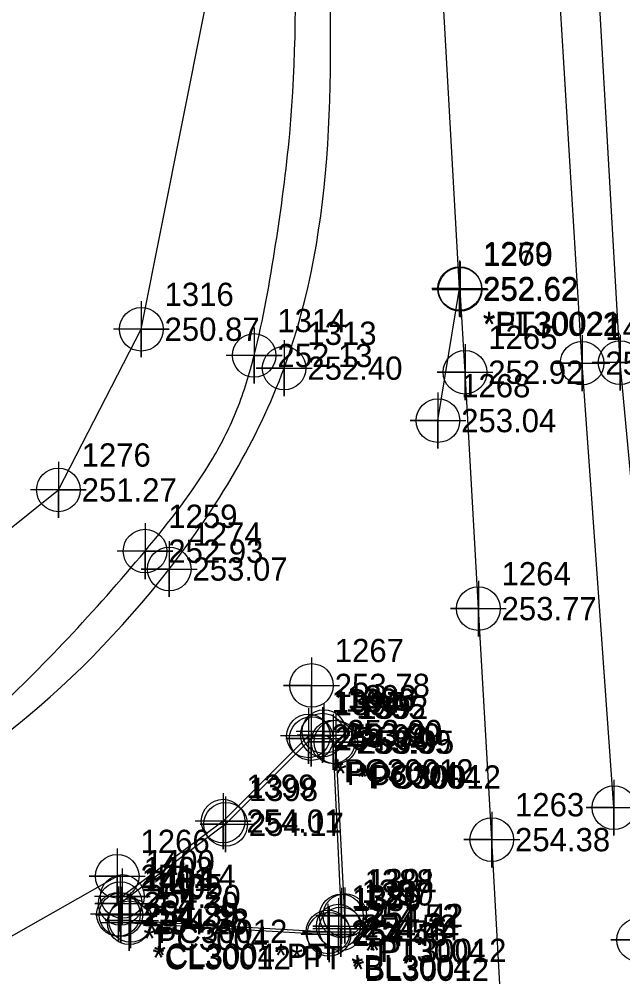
# Model space of a CAD drawing. Extents: x 2130962 to 2131465, y 643052 to 644206.
# Drawn here: x 2131195.3 to 2131260.2, y 643203.3 to 643306.2 of the extents above; entities that cross this region are included whole.
import ezdxf

# ---------------------------------------------------------------- set-up
doc = ezdxf.new("R2010")
doc.units = 0
for name, color, linetype in [('Exist DTM Breakline', 7, 'Continuous'), ('Exist DTM Breakline Cogo Elevation', 7, 'Continuous'), ('Exist DTM Breakline Cogo Number', 7, 'Continuous'), ('Exist DTM Breakline Cogo Point CELL', 7, 'Continuous'), ('Exist Roads Curbs', 7, 'Continuous'), ('Exist Roads Curbs Cogo Comment', 7, 'Continuous'), ('Exist Roads Curbs Cogo Elevation', 7, 'Continuous'), ('Exist Roads Curbs Cogo Number', 7, 'Continuous'), ('Exist Roads Curbs Cogo Point CELL', 7, 'Continuous'), ('Exist Roads EOP', 7, 'Continuous'), ('Exist Roads EOP Cogo Comment', 7, 'Continuous'), ('Exist Roads EOP Cogo Elevation', 7, 'Continuous'), ('Exist Roads EOP Cogo Number', 7, 'Continuous'), ('Exist Roads EOP Cogo Point CELL', 7, 'Continuous'), ('Exist Roads EOT', 7, 'Continuous'), ('Exist Roads EOT Cogo Comment', 7, 'Continuous'), ('Exist Roads EOT Cogo Elevation', 7, 'Continuous'), ('Exist Roads EOT Cogo Number', 7, 'Continuous'), ('Exist Roads EOT Cogo Point CELL', 7, 'Continuous')]:
    doc.layers.add(name, color=color, linetype=linetype)

msp = doc.modelspace()

# ---------------------------------------------------------------- linework, layer by layer
at = {"layer": 'Exist DTM Breakline'}
msp.add_lwpolyline([(2131000.2707, 643222.2884), (2131049.3172, 643219.2511), (2131099.5024, 643216.1866), (2131123.0232, 643217.8518), (2131146.7721, 643223.5416), (2131166.8509, 643229.4959), (2131199.4918, 643255.6512), (2131208.4065, 643272.9132), (2131217.3052, 643317.6851), (2131214.0619, 643367.4973), (2131211.0353, 643416.1836)], dxfattribs=at)
at = {"layer": 'Exist DTM Breakline Cogo Point CELL'}
for points in [[(2131208.4065, 643275.9132), (2131208.4065, 643269.9132), (2131208.4065, 643272.9132), (2131211.4065, 643272.9132), (2131205.4065, 643272.9132)], [(2131199.4918, 643258.6512), (2131199.4918, 643252.6512), (2131199.4918, 643255.6512), (2131202.4918, 643255.6512), (2131196.4918, 643255.6512)]]:
    msp.add_lwpolyline(points, dxfattribs=at)
for centre in [(2131208.4065, 643272.9132), (2131199.4918, 643255.6512)]:
    msp.add_circle(centre, 2.344, dxfattribs=at)
at = {"layer": 'Exist Roads Curbs'}
for points in [[(2131226.6806, 643228.9253), (2131217.4669, 643219.7163), (2131206.1479, 643211.206)], [(2131226.6806, 643228.9253), (2131226.6806, 643228.9253)], [(2131229.9116, 643209.8755), (2131229.0208, 643228.5735)], [(2131207.2468, 643209.3929), (2131228.4737, 643208.158)]]:
    msp.add_lwpolyline(points, dxfattribs=at)
msp.add_arc((2131227.7053, 643227.7822), 1.5352, 31.031398, 131.874567, dxfattribs=at)
at = {"layer": 'Exist Roads Curbs Cogo Point CELL'}
for points in [[(2131227.8758, 643232.3078), (2131227.8758, 643226.3078), (2131227.8758, 643229.3078), (2131225.1458, 643229.3078), (2131230.8758, 643229.3078)], [(2131226.6806, 643231.9253), (2131226.6806, 643225.9253), (2131226.6806, 643228.9253), (2131223.9506, 643228.9253), (2131229.6806, 643228.9253)], [(2131229.0208, 643231.5735), (2131229.0208, 643225.5735), (2131229.0208, 643228.5735), (2131226.2908, 643228.5735), (2131232.0208, 643228.5735)], [(2131217.4669, 643222.7163), (2131217.4669, 643216.7163), (2131217.4669, 643219.7163), (2131214.7369, 643219.7163), (2131220.4669, 643219.7163)], [(2131206.1479, 643214.206), (2131206.1479, 643208.206), (2131206.1479, 643211.206), (2131203.4179, 643211.206), (2131209.1479, 643211.206)], [(2131206.2138, 643213.0076), (2131206.2138, 643207.0076), (2131206.2138, 643210.0076), (2131203.4838, 643210.0076), (2131209.2138, 643210.0076)], [(2131229.9116, 643212.8755), (2131229.9116, 643206.8755), (2131229.9116, 643209.8755), (2131227.1816, 643209.8755), (2131232.9116, 643209.8755)], [(2131207.2468, 643212.3929), (2131207.2468, 643206.3929), (2131207.2468, 643209.3929), (2131204.5168, 643209.3929), (2131210.2468, 643209.3929)], [(2131229.5866, 643211.7744), (2131229.5866, 643205.7744), (2131229.5866, 643208.7744), (2131226.8566, 643208.7744), (2131232.5866, 643208.7744)], [(2131228.4737, 643211.158), (2131228.4737, 643205.158), (2131228.4737, 643208.158), (2131225.7437, 643208.158), (2131231.4737, 643208.158)]]:
    msp.add_lwpolyline(points, dxfattribs=at)
for centre in [(2131226.6806, 643228.9253), (2131227.8758, 643229.3078), (2131229.0208, 643228.5735), (2131217.4669, 643219.7163), (2131206.1479, 643211.206), (2131206.2138, 643210.0076), (2131207.2468, 643209.3929), (2131229.9116, 643209.8755), (2131229.5866, 643208.7744), (2131228.4737, 643208.158)]:
    msp.add_circle(centre, 2.344, dxfattribs=at)
at = {"layer": 'Exist Roads EOP'}
for points in [[(2131264.2715, 643222.5647), (2131259.8757, 643269.3254), (2131257.0196, 643319.4043), (2131254.2561, 643369.6499), (2131250.0777, 643419.4187), (2131246.1511, 643469.0294), (2131240.8382, 643519.1271), (2131234.3674, 643568.5584), (2131226.3321, 643620.1808), (2131217.0271, 643668.7116), (2131205.6213, 643717.607), (2131192.0578, 643767.2595), (2131177.9714, 643815.0911), (2131162.2913, 643862.9344), (2131145.3604, 643910.8486), (2131126.9113, 643957.2915), (2131112.3691, 643996.1228)], [(2131226.3753, 643229.2119), (2131217.1988, 643220.0584), (2131206.3645, 643211.9638)], [(2131226.3753, 643229.2119), (2131226.3753, 643229.2119)], [(2131230.2874, 643209.9228), (2131229.3155, 643228.5471)], [(2131207.1087, 643209.1386), (2131228.5924, 643207.8908)]]:
    msp.add_lwpolyline(points, dxfattribs=at)
msp.add_spline([(2131166.2495, 643216.6951), (2131171.8131, 643218.7244), (2131182.3713, 643223.9726), (2131191.8117, 643231.1489), (2131200.5013, 643239.6993), (2131208.8071, 643249.0697), (2131216.0672, 643259.0032), (2131218.7188, 643264.347), (2131220.5363, 643270.0958), (2131222.8445, 643282.0077), (2131224.3583, 643293.9245), (2131224.8763, 643317.7904), (2131222.0632, 643367.6716), (2131218.5448, 643416.8114), (2131214.3187, 643466.3462), (2131209.1735, 643515.6666), (2131202.7939, 643565.1545), (2131195.0475, 643613.9937), (2131186.4014, 643662.4763), (2131176.0113, 643711.405), (2131164.6154, 643759.8896), (2131151.874, 643807.8526), (2131137.8554, 643855.4065), (2131122.5733, 643902.8574), (2131105.9622, 643949.4862), (2131091.5349, 643988.0437)], degree=3, dxfattribs=at)
at = {"layer": 'Exist Roads EOP Cogo Point CELL'}
for points in [[(2131220.5363, 643273.0958), (2131220.5363, 643267.0958), (2131220.5363, 643270.0958), (2131223.5363, 643270.0958), (2131217.5363, 643270.0958)], [(2131259.8757, 643272.3254), (2131259.8757, 643266.3254), (2131259.8757, 643269.3254), (2131262.8757, 643269.3254), (2131256.8757, 643269.3254)], [(2131208.8071, 643252.0697), (2131208.8071, 643246.0697), (2131208.8071, 643249.0697), (2131211.8071, 643249.0697), (2131205.8071, 643249.0697)], [(2131228.0358, 643232.6796), (2131228.0358, 643226.6796), (2131228.0358, 643229.6796), (2131231.0358, 643229.6796), (2131225.0358, 643229.6796)], [(2131226.3753, 643232.2119), (2131226.3753, 643226.2119), (2131226.3753, 643229.2119), (2131229.3753, 643229.2119), (2131223.3753, 643229.2119)], [(2131229.3155, 643231.5471), (2131229.3155, 643225.5471), (2131229.3155, 643228.5471), (2131232.3155, 643228.5471), (2131226.3155, 643228.5471)], [(2131217.1988, 643223.0584), (2131217.1988, 643217.0584), (2131217.1988, 643220.0584), (2131220.1988, 643220.0584), (2131214.1988, 643220.0584)], [(2131206.3645, 643214.9638), (2131206.3645, 643208.9638), (2131206.3645, 643211.9638), (2131209.3645, 643211.9638), (2131203.3645, 643211.9638)], [(2131205.9466, 643213.0439), (2131205.9466, 643207.0439), (2131205.9466, 643210.0439), (2131208.9466, 643210.0439), (2131202.9466, 643210.0439)], [(2131230.2874, 643212.9228), (2131230.2874, 643206.9228), (2131230.2874, 643209.9228), (2131233.2874, 643209.9228), (2131227.2874, 643209.9228)], [(2131207.1087, 643212.1386), (2131207.1087, 643206.1386), (2131207.1087, 643209.1386), (2131210.1087, 643209.1386), (2131204.1087, 643209.1386)], [(2131228.5924, 643210.8908), (2131228.5924, 643204.8908), (2131228.5924, 643207.8908), (2131231.5924, 643207.8908), (2131225.5924, 643207.8908)], [(2131229.857, 643211.4836), (2131229.857, 643205.4836), (2131229.857, 643208.4836), (2131232.857, 643208.4836), (2131226.857, 643208.4836)]]:
    msp.add_lwpolyline(points, dxfattribs=at)
for centre in [(2131220.5363, 643270.0958), (2131259.8757, 643269.3254), (2131208.8071, 643249.0697), (2131226.3753, 643229.2119), (2131228.0358, 643229.6796), (2131229.3155, 643228.5471), (2131217.1988, 643220.0584), (2131206.3645, 643211.9638), (2131205.9466, 643210.0439), (2131230.2874, 643209.9228), (2131207.1087, 643209.1386), (2131229.857, 643208.4836), (2131228.5924, 643207.8908)]:
    msp.add_circle(centre, 2.344, dxfattribs=at)
at = {"layer": 'Exist Roads EOT'}
msp.add_line((2131259.2129, 643221.5063), (2131255.7894, 643269.2666), dxfattribs=at)
for points in [[(2131255.7894, 643269.2666), (2131252.7511, 643319.2443), (2131249.9083, 643369.5477), (2131246.3502, 643419.1778), (2131242.1933, 643468.6938), (2131237.0867, 643518.9193), (2131230.8671, 643568.2588), (2131222.7066, 643619.1047), (2131213.6442, 643668.3078), (2131202.755, 643717.0933), (2131189.234, 643766.4577), (2131174.9499, 643814.1787), (2131159.2111, 643861.933), (2131141.9103, 643909.6722), (2131123.7008, 643956.0828), (2131104.9436, 644003.1503), (2131086.2706, 644048.8072), (2131065.6997, 644094.9191), (2131044.3618, 644140.0645), (2131021.6804, 644185.4526)], [(2131240.2947, 643263.0991), (2131242.6265, 643277.2895), (2131240.2984, 643318.6562), (2131237.6994, 643363.706)], [(2131179.5807, 643199.2911), (2131198.9377, 643198.0762), (2131247.357, 643195.3668), (2131246.0808, 643218.0694), (2131244.6364, 643242.8933), (2131243.2031, 643268.2965), (2131242.6761, 643277.201)], [(2131179.5807, 643199.2911), (2131205.8187, 643214.1331)]]:
    msp.add_lwpolyline(points, dxfattribs=at)
msp.add_spline([(2131166.718, 643215.2083), (2131172.3866, 643217.1804), (2131211.4056, 643247.1499), (2131223.758, 643268.7314), (2131228.3848, 643317.935), (2131225.533, 643367.8628), (2131222.2486, 643417.1873), (2131217.9619, 643466.6275), (2131212.8794, 643516.2377), (2131206.5633, 643565.5764), (2131198.9021, 643614.6757), (2131189.6851, 643663.4055), (2131179.3985, 643712.1311), (2131168.3085, 643760.7185), (2131155.755, 643808.9129), (2131141.6748, 643856.5528), (2131126.5354, 643904.2758), (2131110.3559, 643951.0191), (2131092.4533, 643998.1348), (2131073.722, 644043.631), (2131053.1654, 644089.359), (2131032.0052, 644134.0908), (2131009.0644, 644179.3802)], degree=3, dxfattribs=at)
at = {"layer": 'Exist Roads EOT Cogo Point CELL'}
for points in [[(2131242.6265, 643280.2895), (2131242.6265, 643274.2895), (2131242.6265, 643277.2895), (2131239.6265, 643277.2895), (2131245.6265, 643277.2895)], [(2131242.6761, 643280.201), (2131242.6761, 643274.201), (2131242.6761, 643277.201), (2131239.6761, 643277.201), (2131245.6761, 643277.201)], [(2131223.758, 643271.7314), (2131223.758, 643265.7314), (2131223.758, 643268.7314), (2131220.758, 643268.7314), (2131226.758, 643268.7314)], [(2131255.7894, 643272.2666), (2131255.7894, 643266.2666), (2131255.7894, 643269.2666), (2131252.7894, 643269.2666), (2131258.7894, 643269.2666)], [(2131243.2031, 643271.2965), (2131243.2031, 643265.2965), (2131243.2031, 643268.2965), (2131240.2031, 643268.2965), (2131246.2031, 643268.2965)], [(2131240.2947, 643266.0991), (2131240.2947, 643260.0991), (2131240.2947, 643263.0991), (2131237.2947, 643263.0991), (2131243.2947, 643263.0991)], [(2131211.4056, 643250.1499), (2131211.4056, 643244.1499), (2131211.4056, 643247.1499), (2131208.4056, 643247.1499), (2131214.4056, 643247.1499)], [(2131244.6364, 643245.8933), (2131244.6364, 643239.8933), (2131244.6364, 643242.8933), (2131241.6364, 643242.8933), (2131247.6364, 643242.8933)], [(2131226.7022, 643237.6427), (2131226.7022, 643231.6427), (2131226.7022, 643234.6427), (2131223.7022, 643234.6427), (2131229.7022, 643234.6427)], [(2131259.2129, 643224.5063), (2131259.2129, 643218.5063), (2131259.2129, 643221.5063), (2131256.2129, 643221.5063), (2131262.2129, 643221.5063)], [(2131246.0808, 643221.0694), (2131246.0808, 643215.0694), (2131246.0808, 643218.0694), (2131243.0808, 643218.0694), (2131249.0808, 643218.0694)], [(2131205.8187, 643217.1331), (2131205.8187, 643211.1331), (2131205.8187, 643214.1331), (2131202.8187, 643214.1331), (2131208.8187, 643214.1331)], [(2131261.865, 643210.302), (2131261.865, 643204.302), (2131261.865, 643207.302), (2131258.865, 643207.302), (2131264.865, 643207.302)]]:
    msp.add_lwpolyline(points, dxfattribs=at)
for centre in [(2131242.6265, 643277.2895), (2131242.6761, 643277.201), (2131255.7894, 643269.2666), (2131223.758, 643268.7314), (2131243.2031, 643268.2965), (2131240.2947, 643263.0991), (2131211.4056, 643247.1499), (2131244.6364, 643242.8933), (2131226.7022, 643234.6427), (2131259.2129, 643221.5063), (2131246.0808, 643218.0694), (2131205.8187, 643214.1331), (2131261.865, 643207.302)]:
    msp.add_circle(centre, 2.344, dxfattribs=at)

# ---------------------------------------------------------------- texts
at = {"layer": 'Exist DTM Breakline Cogo Elevation'}
for s, p in [('250.87', (2131210.9065, 643271.6632)), ('251.27', (2131201.9918, 643254.4012))]:
    msp.add_text(s, height=2.5, dxfattribs=at).set_placement(p)
at = {"layer": 'Exist DTM Breakline Cogo Number'}
for s, p in [('1316', (2131210.9065, 643275.4132)), ('1276', (2131201.9918, 643258.1512))]:
    msp.add_text(s, height=2.5, dxfattribs=at).set_placement(p)
at = {"layer": 'Exist Roads Curbs Cogo Comment'}
for s, p in [('*PC3004', (2131229.1806, 643223.9253)), ('*PC3004', (2131231.5208, 643223.5735)), ('*PC3004', (2131208.6479, 643206.206)), ('*CL3004*PT', (2131209.7468, 643204.3929)), ('*PT3004', (2131232.4116, 643204.8755)), ('*BL3004', (2131230.9737, 643203.158))]:
    msp.add_text(s, height=2.5, dxfattribs=at).set_placement(p)
at = {"layer": 'Exist Roads Curbs Cogo Elevation'}
for s, p in [('254.00', (2131229.1806, 643227.6753)), ('253.99', (2131230.3758, 643228.0578)), ('253.99', (2131231.5208, 643227.3235)), ('254.17', (2131219.9669, 643218.4663)), ('254.30', (2131208.6479, 643209.956)), ('254.35', (2131208.7138, 643208.7576)), ('254.38', (2131209.7468, 643208.1429)), ('254.52', (2131232.4116, 643208.6255)), ('254.53', (2131232.0866, 643207.5244)), ('254.56', (2131230.9737, 643206.908))]:
    msp.add_text(s, height=2.5, dxfattribs=at).set_placement(p)
at = {"layer": 'Exist Roads Curbs Cogo Number'}
for s, p in [('1396', (2131230.3758, 643231.8078)), ('1397', (2131229.1806, 643231.4253)), ('1395', (2131231.5208, 643231.0735)), ('1398', (2131219.9669, 643222.2163)), ('1403', (2131208.6479, 643213.706)), ('1404', (2131208.7138, 643212.5076)), ('1388', (2131232.4116, 643212.3755)), ('1405', (2131209.7468, 643211.8929)), ('1387', (2131232.0866, 643211.2744)), ('1386', (2131230.9737, 643210.658))]:
    msp.add_text(s, height=2.5, dxfattribs=at).set_placement(p)
at = {"layer": 'Exist Roads EOP Cogo Comment'}
for s, p in [('*PC30012', (2131228.8753, 643224.2119)), ('*PC30012', (2131231.8155, 643223.5471)), ('*PC30012', (2131208.8645, 643206.9638)), ('*CL30012*PT', (2131209.6087, 643204.1386)), ('*PT30012', (2131232.7874, 643204.9228)), ('*BL30012', (2131231.0924, 643202.8908))]:
    msp.add_text(s, height=2.5, dxfattribs=at).set_placement(p)
at = {"layer": 'Exist Roads EOP Cogo Elevation'}
for s, p in [('252.13', (2131223.0363, 643268.8458)), ('252.93', (2131211.3071, 643247.8197)), ('253.92', (2131228.8753, 643227.9619)), ('253.90', (2131230.5358, 643228.4296)), ('253.95', (2131231.8155, 643227.2971)), ('254.01', (2131219.6988, 643218.8084)), ('254.20', (2131208.8645, 643210.7138)), ('254.29', (2131208.4466, 643208.7939)), ('254.42', (2131232.7874, 643208.6728)), ('254.26', (2131209.6087, 643207.8886)), ('254.44', (2131232.357, 643207.2336)), ('254.43', (2131231.0924, 643206.6408))]:
    msp.add_text(s, height=2.5, dxfattribs=at).set_placement(p)
at = {"layer": 'Exist Roads EOP Cogo Number'}
for s, p in [('1314', (2131223.0363, 643272.5958)), ('1259', (2131211.3071, 643251.5697)), ('1393', (2131230.5358, 643232.1796)), ('1394', (2131228.8753, 643231.7119)), ('1392', (2131231.8155, 643231.0471)), ('1399', (2131219.6988, 643222.5584)), ('1400', (2131208.8645, 643214.4638)), ('1401', (2131208.4466, 643212.5439)), ('1391', (2131232.7874, 643212.4228)), ('1402', (2131209.6087, 643211.6386)), ('1389', (2131231.0924, 643210.3908)), ('1390', (2131232.357, 643210.9836))]:
    msp.add_text(s, height=2.5, dxfattribs=at).set_placement(p)
at = {"layer": 'Exist Roads EOT Cogo Comment'}
for s, p in [('*PT30021', (2131245.1265, 643272.2895)), ('*EL30022', (2131245.1761, 643272.201))]:
    msp.add_text(s, height=2.5, dxfattribs=at).set_placement(p)
at = {"layer": 'Exist Roads EOT Cogo Elevation'}
for s, p in [('252.62', (2131245.1265, 643276.0395)), ('252.62', (2131245.1761, 643275.951)), ('252.83', (2131258.2894, 643268.0166)), ('252.40', (2131226.258, 643267.4814)), ('252.92', (2131245.7031, 643267.0465)), ('253.04', (2131242.7947, 643261.8491)), ('253.07', (2131213.9056, 643245.8999)), ('253.77', (2131247.1364, 643241.6433)), ('253.78', (2131229.2022, 643233.3927)), ('254.38', (2131248.5808, 643216.8194)), ('254.14', (2131208.3187, 643212.8831))]:
    msp.add_text(s, height=2.5, dxfattribs=at).set_placement(p)
at = {"layer": 'Exist Roads EOT Cogo Number'}
for s, p in [('1269', (2131245.1265, 643279.7895)), ('1270', (2131245.1761, 643279.701)), ('1313', (2131226.258, 643271.2314)), ('1406', (2131258.2894, 643271.7666)), ('1265', (2131245.7031, 643270.7965)), ('1268', (2131242.7947, 643265.5991)), ('1274', (2131213.9056, 643249.6499)), ('1264', (2131247.1364, 643245.3933)), ('1267', (2131229.2022, 643237.1427)), ('1263', (2131248.5808, 643220.5694)), ('1266', (2131208.3187, 643216.6331))]:
    msp.add_text(s, height=2.5, dxfattribs=at).set_placement(p)

doc.saveas('drawing.dxf')
